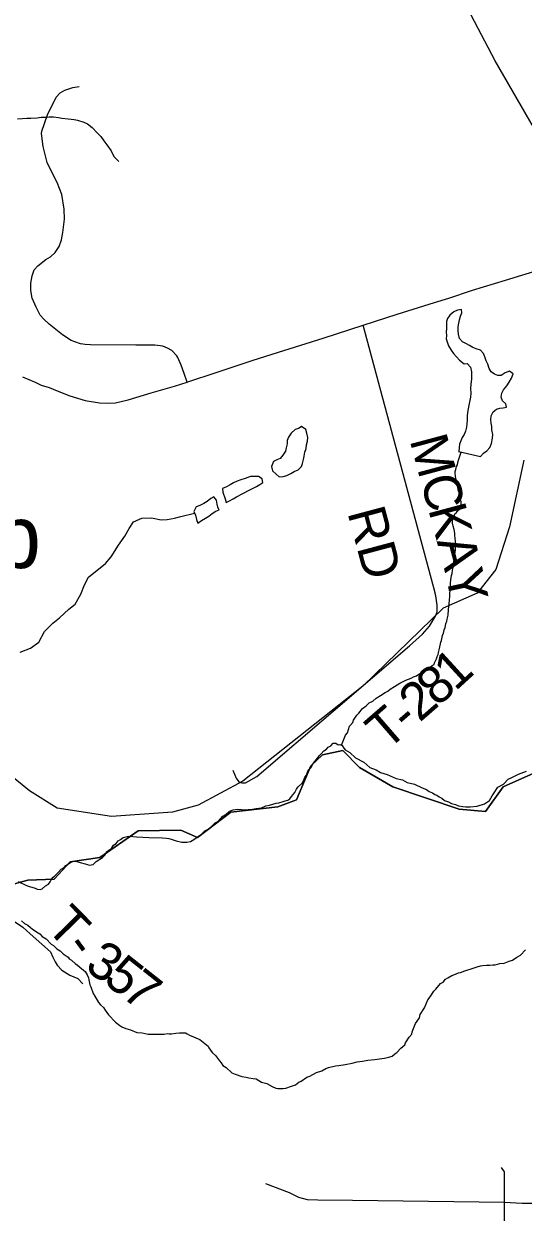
# Model space of a CAD drawing. Extents: x 0 to 34, y 0 to 22.
# Drawn here: x 5.489 to 6.245, y 18.554 to 20.352 of the extents above; entities that cross this region are included whole.
import ezdxf

# ---------------------------------------------------------------- set-up
doc = ezdxf.new("R2010")
doc.units = 0
for name, color, linetype in [('GM_X_Corporation', 7, 'Continuous'), ('GM_X_Minor_Lake', 7, 'Continuous'), ('GM_X_Minor_Lake_Text', 7, 'Continuous'), ('GM_X_Minor_River', 7, 'Continuous'), ('GM_X_Rail_Line', 7, 'Continuous'), ('GM_X_Township_Road', 7, 'Continuous'), ('GM_X_Township_Road_Text', 7, 'Continuous'), ('GM_X_US_Route', 7, 'Continuous')]:
    doc.layers.add(name, color=color, linetype=linetype)

msp = doc.modelspace()

# ---------------------------------------------------------------- linework, layer by layer
at = {"layer": 'GM_X_Corporation'}
for points in [[(6.2834, 19.2286), (6.2142, 19.1977), (6.1875, 19.1605), (6.148, 19.1641), (6.0474, 19.1975), (5.9969, 19.2271), (5.9718, 19.2529), (5.9409, 19.2461), (5.9236, 19.2297), (5.9019, 19.178), (5.8737, 19.1674), (5.8025, 19.1593), (5.7522, 19.121), (5.7269, 19.1323), (5.6622, 19.1314), (5.6043, 19.0909), (5.5594, 19.0843), (5.535, 19.0581), (5.4955, 19.0564), (5.4436, 19.0427)], [(5.4436, 19.0427), (5.4955, 19.0564), (5.535, 19.0581), (5.5594, 19.0843), (5.6043, 19.0909), (5.6622, 19.1314), (5.7269, 19.1323), (5.7522, 19.121), (5.8025, 19.1593), (5.8737, 19.1674), (5.9019, 19.178), (5.9236, 19.2297), (5.9409, 19.2461), (5.9718, 19.2529), (5.9969, 19.2271), (6.0474, 19.1975), (6.148, 19.1641), (6.1875, 19.1605), (6.2142, 19.1977), (6.2834, 19.2286)]]:
    msp.add_lwpolyline(points, dxfattribs=at)
at = {"layer": 'GM_X_Minor_Lake'}
for p, q in [((5.9096, 19.7426), (5.9046, 19.7398)), ((5.8464, 19.6549), (5.8509, 19.6578))]:
    msp.add_line(p, q, dxfattribs=at)
for points in [[(6.18, 19.6976), (6.1849, 19.7023), (6.1899, 19.706), (6.1945, 19.7109), (6.1969, 19.7169), (6.1981, 19.7249), (6.1986, 19.7306), (6.1975, 19.7378), (6.1972, 19.7428), (6.1962, 19.7477), (6.1958, 19.7526), (6.1963, 19.7587), (6.1994, 19.7651), (6.2044, 19.7692), (6.2094, 19.7703), (6.2143, 19.771), (6.2197, 19.772), (6.2182, 19.777), (6.2134, 19.7816), (6.2112, 19.7873), (6.2124, 19.7934), (6.2147, 19.7983), (6.2198, 19.8043), (6.2236, 19.8099), (6.2268, 19.8156), (6.2295, 19.8224), (6.2239, 19.8266), (6.2174, 19.8237), (6.2112, 19.82), (6.2063, 19.8201), (6.2014, 19.822), (6.1965, 19.8255), (6.1931, 19.8305), (6.191, 19.837), (6.1887, 19.842), (6.1869, 19.8481), (6.1847, 19.853), (6.1799, 19.8584), (6.1738, 19.86), (6.1685, 19.8624), (6.1636, 19.8651), (6.1579, 19.8682), (6.1527, 19.871), (6.1482, 19.876), (6.1467, 19.8824), (6.1464, 19.8881), (6.1465, 19.8935), (6.1474, 19.8991), (6.1482, 19.9041), (6.1498, 19.9094), (6.1518, 19.9146), (6.1514, 19.9196), (6.1454, 19.9189), (6.14, 19.916), (6.1338, 19.9111), (6.13, 19.9062), (6.1288, 19.9013), (6.1286, 19.8911), (6.1282, 19.8854), (6.1285, 19.8804), (6.1284, 19.8755), (6.1295, 19.8706), (6.1317, 19.8648), (6.1358, 19.8583), (6.1391, 19.8529), (6.144, 19.8483), (6.1485, 19.8429), (6.1552, 19.8375), (6.1602, 19.8378), (6.165, 19.8324), (6.1665, 19.8256), (6.1663, 19.8142), (6.1654, 19.8066), (6.165, 19.8002), (6.1653, 19.7933), (6.1648, 19.7873), (6.164, 19.782), (6.1627, 19.7752), (6.1615, 19.7695), (6.1607, 19.7638), (6.1602, 19.7585), (6.1601, 19.7528), (6.1597, 19.7467), (6.1588, 19.7418), (6.1572, 19.7357), (6.1553, 19.7308), (6.1525, 19.7259), (6.1502, 19.721), (6.1486, 19.7161), (6.1481, 19.7112), (6.1473, 19.7047)], [(6.1799, 19.6975), (6.1849, 19.7023), (6.1899, 19.706), (6.1945, 19.7109), (6.1969, 19.7169), (6.1981, 19.7249), (6.1986, 19.7306), (6.1975, 19.7378), (6.1972, 19.7428), (6.1962, 19.7477), (6.1958, 19.7526), (6.1963, 19.7587), (6.1994, 19.7651), (6.2044, 19.7692), (6.2094, 19.7703), (6.2143, 19.771), (6.2197, 19.772), (6.2182, 19.777), (6.2134, 19.7816), (6.2112, 19.7873), (6.2124, 19.7934), (6.2147, 19.7983), (6.2198, 19.8043), (6.2236, 19.8099), (6.2268, 19.8156), (6.2295, 19.8224), (6.2239, 19.8266), (6.2174, 19.8237), (6.2112, 19.82), (6.2063, 19.8201), (6.2014, 19.822), (6.1965, 19.8255), (6.1931, 19.8305), (6.191, 19.837), (6.1887, 19.842), (6.1869, 19.8481), (6.1847, 19.853), (6.1799, 19.8584), (6.1738, 19.86), (6.1685, 19.8624), (6.1636, 19.8651), (6.1579, 19.8682), (6.1527, 19.871), (6.1482, 19.876), (6.1467, 19.8824), (6.1464, 19.8881), (6.1465, 19.8935), (6.1474, 19.8991), (6.1482, 19.9041), (6.1498, 19.9094), (6.1518, 19.9146), (6.1514, 19.9196), (6.1454, 19.9189), (6.14, 19.916), (6.1338, 19.9111), (6.13, 19.9062), (6.1288, 19.9013), (6.1286, 19.8911), (6.1282, 19.8854), (6.1285, 19.8804), (6.1284, 19.8755), (6.1295, 19.8706), (6.1317, 19.8648), (6.1358, 19.8583), (6.1391, 19.8529), (6.144, 19.8483), (6.1485, 19.8429), (6.1552, 19.8375), (6.1602, 19.8378), (6.165, 19.8324), (6.1665, 19.8256), (6.1663, 19.8142), (6.1654, 19.8066), (6.165, 19.8002), (6.1653, 19.7933), (6.1648, 19.7873), (6.164, 19.782), (6.1627, 19.7752), (6.1615, 19.7695), (6.1607, 19.7638), (6.1602, 19.7585), (6.1601, 19.7528), (6.1597, 19.7467), (6.1588, 19.7418), (6.1572, 19.7357), (6.1553, 19.7308), (6.1525, 19.7259), (6.1502, 19.721), (6.1486, 19.7161), (6.1481, 19.7112), (6.1473, 19.7044), (6.1477, 19.7044)], [(5.9099, 19.7428), (5.9046, 19.7398), (5.8996, 19.738), (5.8938, 19.7328), (5.8899, 19.7268), (5.8876, 19.7215), (5.8875, 19.7166), (5.8863, 19.7105), (5.8851, 19.7056), (5.8812, 19.6996), (5.8769, 19.6943), (5.872, 19.6925), (5.867, 19.6899), (5.8639, 19.6823), (5.8657, 19.6759), (5.8709, 19.6705), (5.8758, 19.6666), (5.8815, 19.6673), (5.8872, 19.6687), (5.893, 19.6717), (5.8983, 19.6746), (5.9041, 19.6772), (5.9094, 19.6821), (5.9107, 19.687), (5.9126, 19.693), (5.9135, 19.6979), (5.9143, 19.704), (5.9163, 19.7097), (5.9171, 19.715), (5.9184, 19.7207), (5.9188, 19.726), (5.9174, 19.7328), (5.9159, 19.7382), (5.9096, 19.7426)], [(5.9046, 19.7398), (5.8996, 19.738), (5.8938, 19.7328), (5.8899, 19.7268), (5.8876, 19.7215), (5.8875, 19.7166), (5.8863, 19.7105), (5.8851, 19.7056), (5.8812, 19.6996), (5.8769, 19.6943), (5.872, 19.6925), (5.867, 19.6899), (5.8639, 19.6823), (5.8657, 19.6759), (5.8709, 19.6705), (5.8758, 19.6666), (5.8815, 19.6673), (5.8872, 19.6687), (5.893, 19.6717), (5.8983, 19.6746), (5.9041, 19.6772), (5.9094, 19.6821), (5.9107, 19.687), (5.9126, 19.693), (5.9135, 19.6979), (5.9143, 19.704), (5.9163, 19.7097), (5.9171, 19.715), (5.9184, 19.7207), (5.9188, 19.726), (5.9174, 19.7328), (5.9159, 19.7382), (5.9096, 19.7426)], [(6.1473, 19.7047), (6.18, 19.6976)], [(5.8509, 19.6578), (5.8499, 19.6636), (5.8443, 19.6671), (5.8386, 19.6672), (5.8321, 19.6669), (5.8241, 19.6643), (5.8176, 19.6622), (5.8119, 19.66), (5.8065, 19.6574), (5.8015, 19.6544), (5.7958, 19.6515), (5.79, 19.6489), (5.7903, 19.6432), (5.794, 19.6333), (5.7954, 19.6279), (5.8004, 19.6301), (5.8058, 19.6331), (5.8108, 19.6364), (5.8207, 19.6416), (5.8314, 19.6468), (5.8414, 19.6519), (5.8464, 19.6549)], [(5.8509, 19.6578), (5.8499, 19.6636), (5.8443, 19.6671), (5.8386, 19.6672), (5.8321, 19.6669), (5.8241, 19.6643), (5.8176, 19.6622), (5.8119, 19.66), (5.8065, 19.6574), (5.8015, 19.6544), (5.7958, 19.6515), (5.79, 19.6489), (5.7903, 19.6432), (5.794, 19.6333), (5.7954, 19.6279), (5.8004, 19.6301), (5.8058, 19.6331), (5.8108, 19.6364), (5.8207, 19.6416), (5.8314, 19.6468), (5.8414, 19.6519), (5.8464, 19.6549), (5.851, 19.6579)], [(5.7845, 19.6173), (5.7828, 19.6205), (5.7817, 19.6255), (5.7807, 19.6312), (5.7769, 19.6362), (5.772, 19.6336), (5.7666, 19.6295), (5.7616, 19.6261), (5.7555, 19.6232), (5.7501, 19.621), (5.7466, 19.6142), (5.7488, 19.6085), (5.7506, 19.602), (5.7524, 19.5967), (5.7582, 19.6008), (5.7639, 19.6041), (5.7693, 19.6071), (5.7743, 19.6112), (5.7797, 19.6145), (5.7846, 19.6167)], [(5.7845, 19.6173), (5.7828, 19.6205), (5.7817, 19.6255), (5.7807, 19.6312), (5.7769, 19.6362), (5.772, 19.6336), (5.7666, 19.6295), (5.7616, 19.6261), (5.7555, 19.6232), (5.7501, 19.621), (5.7466, 19.6142), (5.7488, 19.6085), (5.7506, 19.602), (5.7524, 19.5967), (5.7582, 19.6008), (5.7639, 19.6041), (5.7693, 19.6071), (5.7743, 19.6112), (5.7797, 19.6145), (5.7846, 19.6167)], [(5.7846, 19.6167), (5.7845, 19.6173)], [(5.7845, 19.6173), (5.7847, 19.6167)]]:
    msp.add_lwpolyline(points, dxfattribs=at)
at = {"layer": 'GM_X_Minor_River'}
for points in [[(5.48, 20.208), (5.4937, 20.2089), (5.5001, 20.2092), (5.5093, 20.2098), (5.5154, 20.2104), (5.523, 20.2107), (5.5279, 20.211), (5.5344, 20.2109), (5.542, 20.21), (5.5469, 20.2091), (5.5564, 20.2082), (5.5655, 20.2073), (5.5704, 20.2061), (5.5799, 20.2032), (5.5855, 20.2005), (5.5926, 20.195), (5.6001, 20.1869), (5.6057, 20.1815), (5.6106, 20.1749), (5.615, 20.1688), (5.6217, 20.1599), (5.6254, 20.1511), (5.6332, 20.1437)], [(6.1452, 19.6847), (6.1456, 19.6882), (6.1468, 19.6919), (6.1484, 19.6965), (6.1509, 19.7039)], [(5.9699, 19.2607), (5.9759, 19.2758), (5.9787, 19.2792), (5.9822, 19.2894), (5.9869, 19.295), (5.9881, 19.2984), (5.9932, 19.3063), (5.9959, 19.3093), (6.0017, 19.316), (6.0071, 19.3201), (6.0117, 19.3246), (6.0171, 19.3275), (6.0221, 19.3316), (6.0287, 19.3361), (6.036, 19.3405), (6.0398, 19.3424), (6.0436, 19.3453), (6.0498, 19.3494), (6.0579, 19.3546), (6.0674, 19.359), (6.0755, 19.3619), (6.0789, 19.3641), (6.0835, 19.3656), (6.0897, 19.37), (6.0943, 19.3715), (6.0977, 19.3737), (6.1004, 19.3748), (6.1039, 19.3785), (6.107, 19.3811), (6.11, 19.3826), (6.1108, 19.3852), (6.1136, 19.3913), (6.1148, 19.3947), (6.116, 19.3977), (6.1168, 19.4011), (6.1181, 19.4072), (6.1201, 19.4163), (6.1209, 19.4189), (6.1226, 19.4265), (6.1242, 19.4303), (6.125, 19.4352), (6.1266, 19.4386), (6.1278, 19.4443), (6.1294, 19.4484), (6.1295, 19.4515), (6.1311, 19.4575), (6.1316, 19.4659), (6.1329, 19.475), (6.133, 19.4803), (6.1335, 19.486), (6.1335, 19.4898), (6.134, 19.4951), (6.1344, 19.4982), (6.1345, 19.5024), (6.1349, 19.5058), (6.1354, 19.5107), (6.1363, 19.5175), (6.1371, 19.5202), (6.1379, 19.5255), (6.1388, 19.5297), (6.1388, 19.5323), (6.1401, 19.5407), (6.1409, 19.5448), (6.1414, 19.5494), (6.1418, 19.5521), (6.1423, 19.5566), (6.1424, 19.5642), (6.1421, 19.5684), (6.1418, 19.5741), (6.1415, 19.5775), (6.1411, 19.5814), (6.1405, 19.5871), (6.139, 19.592), (6.138, 19.5966), (6.1377, 19.6012), (6.1385, 19.6042), (6.1401, 19.6069), (6.1413, 19.6106), (6.144, 19.6125), (6.1459, 19.6159), (6.1486, 19.6177), (6.1502, 19.6204), (6.151, 19.6261), (6.1507, 19.6287), (6.1496, 19.6329), (6.1483, 19.6417), (6.1468, 19.6448), (6.1457, 19.6505), (6.1447, 19.6543), (6.1436, 19.66), (6.1429, 19.6635), (6.1422, 19.6688), (6.1419, 19.6719), (6.142, 19.6749), (6.1428, 19.6776), (6.1436, 19.6821), (6.1452, 19.6847)], [(5.4838, 19.4015), (5.4995, 19.4073), (5.5118, 19.4166), (5.5208, 19.4328), (5.5332, 19.4451), (5.5432, 19.4533), (5.5572, 19.4664), (5.5672, 19.4742), (5.5758, 19.4889), (5.581, 19.5032), (5.5873, 19.5149), (5.6128, 19.5354), (5.6213, 19.5455), (5.6327, 19.5631), (5.642, 19.577), (5.6487, 19.5887), (5.655, 19.5985), (5.668, 19.604), (5.6825, 19.6045), (5.6969, 19.6015), (5.7064, 19.6021), (5.7171, 19.6042), (5.7266, 19.6067), (5.7476, 19.6117)], [(5.9261, 19.2314), (5.9296, 19.2359), (5.9335, 19.2412), (5.9366, 19.2449), (5.9393, 19.2475), (5.9432, 19.2524), (5.9474, 19.2546), (5.9498, 19.2576), (5.9536, 19.2598), (5.9575, 19.2636), (5.9613, 19.2639), (5.9647, 19.2611), (5.9673, 19.2619), (5.9707, 19.2603), (5.9733, 19.2564), (5.9756, 19.2537), (5.9827, 19.2498), (5.9913, 19.2417), (6.0038, 19.235), (6.0128, 19.2272), (6.0222, 19.2232), (6.029, 19.2193), (6.0392, 19.2165), (6.0528, 19.2105), (6.0622, 19.2081), (6.0694, 19.2045), (6.0804, 19.2017), (6.0917, 19.1962), (6.0985, 19.1937), (6.1026, 19.1906), (6.1075, 19.1886), (6.1109, 19.1863), (6.1143, 19.1851), (6.1177, 19.1824), (6.1218, 19.1804), (6.1256, 19.1773), (6.1316, 19.1753), (6.1365, 19.1725), (6.1422, 19.1709), (6.1467, 19.1689), (6.1536, 19.1681), (6.1581, 19.1676), (6.1646, 19.1675), (6.1749, 19.1684), (6.1863, 19.172), (6.1936, 19.1769), (6.1979, 19.184), (6.1999, 19.187), (6.2065, 19.1972), (6.215, 19.202), (6.2219, 19.2095), (6.2277, 19.212), (6.2376, 19.2168), (6.2415, 19.2182), (6.2495, 19.2215)], [(5.481, 19.0544), (5.4935, 19.0484), (5.498, 19.0468), (5.5063, 19.0444), (5.5097, 19.0432), (5.5143, 19.0427), (5.5173, 19.0435), (5.5223, 19.0479), (5.5266, 19.0505), (5.5293, 19.0543), (5.5324, 19.0599), (5.5355, 19.0625), (5.5409, 19.0678), (5.5456, 19.0734), (5.5502, 19.0756), (5.5529, 19.079), (5.5571, 19.0812), (5.5606, 19.0838), (5.5648, 19.0852), (5.5697, 19.0848), (5.5746, 19.0831), (5.5822, 19.0815), (5.5856, 19.0803), (5.5883, 19.0795), (5.594, 19.0801), (5.5986, 19.0846), (5.6082, 19.0909), (5.6125, 19.095), (5.6137, 19.0988), (5.6179, 19.1018), (5.6218, 19.1044), (5.6249, 19.1096), (5.6291, 19.1122), (5.6318, 19.116), (5.6357, 19.1182), (5.6395, 19.1212), (5.6476, 19.1233), (5.654, 19.1228), (5.6597, 19.122), (5.6696, 19.1214), (5.6783, 19.1209), (5.6988, 19.1205), (5.7053, 19.12), (5.7087, 19.1196), (5.7121, 19.1188), (5.72, 19.116), (5.7284, 19.1139), (5.7329, 19.1138), (5.736, 19.1142), (5.7413, 19.1152), (5.7463, 19.1182), (5.7501, 19.1204), (5.7582, 19.1263), (5.7629, 19.1312), (5.7702, 19.1349), (5.7787, 19.1431), (5.784, 19.146), (5.7902, 19.1535), (5.7948, 19.1557), (5.8003, 19.161), (5.806, 19.1628), (5.8132, 19.1638), (5.8185, 19.1633), (5.822, 19.1632), (5.8288, 19.1635), (5.8322, 19.1634), (5.8406, 19.1652), (5.849, 19.1662), (5.8555, 19.1691), (5.8609, 19.1702), (5.8708, 19.173), (5.875, 19.1737), (5.8815, 19.1755), (5.8845, 19.1766), (5.8887, 19.1777), (5.8918, 19.1795), (5.8942, 19.1833), (5.8992, 19.1893), (5.9019, 19.1942), (5.9039, 19.1972), (5.9109, 19.2039), (5.9136, 19.2092), (5.9144, 19.2122), (5.9171, 19.2156), (5.9195, 19.2228), (5.9238, 19.2269), (5.9261, 19.2314)], [(5.4857, 18.9953), (5.4902, 18.9911), (5.4955, 18.9887), (5.4996, 18.9848), (5.5022, 18.9829), (5.5086, 18.9782), (5.5135, 18.9754), (5.5172, 18.9716), (5.5233, 18.968), (5.5307, 18.9599), (5.5341, 18.958), (5.5394, 18.9529), (5.5443, 18.9498), (5.5487, 18.9451), (5.5566, 18.9401), (5.5581, 18.9374), (5.5615, 18.9354), (5.5675, 18.93), (5.5701, 18.9284), (5.5742, 18.9249), (5.5795, 18.9206), (5.5821, 18.9183), (5.5851, 18.9133), (5.5873, 18.9087), (5.5876, 18.906), (5.5894, 18.8984), (5.5905, 18.8953), (5.5941, 18.885), (5.5967, 18.8812), (5.6022, 18.8716), (5.6052, 18.8681), (5.6097, 18.8638), (5.6123, 18.86), (5.6175, 18.8527), (5.628, 18.8418), (5.6347, 18.8368), (5.6377, 18.8348), (5.6434, 18.832), (5.6506, 18.8304), (5.6604, 18.8264), (5.6684, 18.8255), (5.6775, 18.8238), (5.698, 18.8235), (5.7018, 18.8238), (5.7064, 18.8245), (5.7094, 18.824), (5.7125, 18.8244), (5.7193, 18.8254), (5.725, 18.8257), (5.7307, 18.8259), (5.7338, 18.8255), (5.7364, 18.8239), (5.7398, 18.822), (5.7557, 18.8156), (5.7631, 18.8094), (5.7684, 18.8055), (5.7691, 18.8028), (5.7743, 18.7959), (5.7792, 18.7916), (5.7855, 18.7831), (5.7878, 18.7804), (5.7903, 18.7762), (5.7952, 18.7731), (5.8042, 18.7653), (5.8091, 18.7633), (5.819, 18.7597), (5.8258, 18.7585), (5.8296, 18.7576), (5.8364, 18.7568), (5.8409, 18.7559), (5.8488, 18.7512), (5.8568, 18.7488), (5.8651, 18.7445), (5.8704, 18.7421), (5.8738, 18.7413), (5.8814, 18.7415), (5.8856, 18.7422), (5.894, 18.7451), (5.9005, 18.7469), (5.9051, 18.751), (5.9089, 18.7528), (5.9174, 18.7584), (5.922, 18.7602), (5.932, 18.7657), (5.94, 18.7682), (5.9461, 18.7719), (5.9503, 18.773), (5.961, 18.7759), (5.966, 18.7765), (5.9755, 18.7779), (5.9858, 18.78), (5.9938, 18.7818)], [(5.9938, 18.7818), (6.0018, 18.7828), (6.0095, 18.7845), (6.0201, 18.7855), (6.0308, 18.7868), (6.035, 18.7871), (6.0415, 18.7889), (6.0464, 18.7903), (6.0507, 18.7937), (6.0538, 18.7959), (6.0596, 18.8023), (6.0657, 18.8075), (6.0669, 18.8105), (6.0724, 18.8192), (6.0763, 18.8237), (6.0767, 18.8271), (6.0819, 18.8399), (6.0877, 18.8482), (6.0889, 18.8535), (6.0956, 18.8636), (6.1007, 18.8757), (6.1038, 18.8799), (6.1097, 18.8885), (6.1128, 18.8919), (6.1194, 18.9001), (6.1236, 18.9023), (6.1271, 18.9068), (6.1306, 18.9087), (6.1367, 18.9124), (6.1398, 18.9135), (6.1467, 18.9164), (6.1497, 18.9171), (6.1566, 18.9192), (6.1688, 18.9236), (6.1749, 18.9254), (6.1803, 18.9272), (6.1837, 18.9275), (6.189, 18.9278), (6.194, 18.9281), (6.1986, 18.9284), (6.2024, 18.9287), (6.2096, 18.9305), (6.2161, 18.9311), (6.2234, 18.9341), (6.2283, 18.9355), (6.2349, 18.9403), (6.2406, 18.9433), (6.2484, 18.9511)]]:
    msp.add_lwpolyline(points, dxfattribs=at)
at = {"layer": 'GM_X_Rail_Line'}
msp.add_lwpolyline([(6.2458, 19.6916), (6.2238, 19.5908), (6.2031, 19.5265), (6.1749, 19.4905), (6.1239, 19.468), (6.0022, 19.3502), (5.8206, 19.2063), (5.7529, 19.1701), (5.7143, 19.1592), (5.6222, 19.1528), (5.5397, 19.1654), (5.498, 19.1918), (5.4679, 19.2162)], dxfattribs=at)
at = {"layer": 'GM_X_Township_Road'}
msp.add_line((6.1114, 19.4912), (6.0025, 19.8962), dxfattribs=at)
for points in [[(6.367, 20.0102), (6.2024, 20.2959), (6.1451, 20.4046)], [(5.7363, 19.81), (5.7319, 19.8228), (5.7273, 19.8356), (5.7225, 19.8472), (5.7208, 19.8498), (5.7131, 19.8575), (5.7069, 19.8614), (5.6995, 19.8643), (5.6876, 19.866), (5.6589, 19.8657), (5.5901, 19.8663), (5.5819, 19.8668), (5.5751, 19.8677), (5.5666, 19.8708), (5.5612, 19.8728), (5.5478, 19.8816), (5.5279, 19.8975), (5.5194, 19.9052), (5.5143, 19.9111), (5.508, 19.9234), (5.5021, 19.937), (5.4998, 19.9486), (5.4998, 19.9594), (5.5018, 19.9708), (5.5049, 19.9799), (5.5106, 19.9858), (5.5225, 19.9955), (5.5296, 19.9995), (5.5367, 20.0057), (5.5427, 20.0148), (5.5461, 20.025), (5.5484, 20.0361), (5.5509, 20.0563), (5.5504, 20.0714), (5.5467, 20.0935), (5.5399, 20.1117), (5.5285, 20.1333), (5.5245, 20.1421), (5.5188, 20.1662), (5.516, 20.1858), (5.5166, 20.1895), (5.5254, 20.2139), (5.5381, 20.2409), (5.5441, 20.2472), (5.5512, 20.2514), (5.5637, 20.2557), (5.5731, 20.257)], [(5.8148, 19.2052), (5.8193, 19.204), (5.8246, 19.2038), (5.8416, 19.2133), (6.0729, 19.4111), (6.0923, 19.4285), (6.1029, 19.4407), (6.112, 19.4561), (6.1144, 19.4625), (6.1147, 19.4723), (6.1128, 19.4864), (6.1117, 19.4902), (6.1114, 19.4912)], [(5.8054, 19.2229), (5.8104, 19.2107), (5.8148, 19.2052)], [(5.4473, 19.0042), (5.4483, 19.0038), (5.4633, 18.9999), (5.4766, 18.9931), (5.4878, 18.9854), (5.499, 18.9752), (5.5165, 18.9597), (5.5296, 18.9482), (5.5332, 18.94), (5.5367, 18.933), (5.5396, 18.9278), (5.5466, 18.9205), (5.5589, 18.913), (5.5708, 18.9076), (5.5788, 18.8996)], [(5.8547, 18.5979), (5.8909, 18.5841), (5.905, 18.5769), (5.9177, 18.5736), (5.9343, 18.5729), (5.9865, 18.5725), (6.2165, 18.5693), (6.2433, 18.5678), (6.2723, 18.5678), (6.2915, 18.5664), (6.3071, 18.5678), (6.319, 18.5711), (6.3321, 18.5816), (6.3425, 18.5956), (6.3481, 18.6528), (6.3457, 18.6879)], [(6.2584, 18.389), (6.2181, 18.4696), (6.2158, 18.4819), (6.2165, 18.5693), (6.2163, 18.6154), (6.2119, 18.6221)]]:
    msp.add_lwpolyline(points, dxfattribs=at)
at = {"layer": 'GM_X_US_Route'}
msp.add_lwpolyline([(5.4873, 19.8179), (5.5063, 19.8097), (5.5156, 19.8053), (5.5276, 19.8016), (5.5398, 19.7965), (5.559, 19.7892), (5.5821, 19.7822), (5.604, 19.7784), (5.6153, 19.7778), (5.628, 19.7787), (5.6471, 19.783), (5.6822, 19.7938), (5.7174, 19.8037), (5.7363, 19.81), (5.7391, 19.811), (5.7789, 19.824), (5.8363, 19.8429), (5.8824, 19.8577), (5.9423, 19.8765), (6.0025, 19.8962), (6.054, 19.9126), (6.1105, 19.9302), (6.1321, 19.9366), (6.1682, 19.949), (6.2178, 19.9642), (6.2737, 19.9811)], dxfattribs=at)

# ---------------------------------------------------------------- texts
at = {"layer": 'GM_X_Minor_Lake_Text'}
msp.add_text('Hilltop', height=0.09469, rotation=359.9965, dxfattribs=at).set_placement((5.1633, 19.5287))
at = {"layer": 'GM_X_Township_Road_Text'}
for s, height, rotation, p in [('M', 0.0568, 284.9976, (6.0727, 19.7224)), ('C', 0.0568, 284.9943, (6.0887, 19.6628)), ('RD', 0.05682, 284.9946, (5.9785, 19.613)), ('K', 0.0568, 284.9958, (6.1008, 19.6178)), ('A', 0.0568, 284.9701, (6.1137, 19.5695)), ('Y', 0.0568, 282.0436, (6.1264, 19.5219)), ('1', 0.0568, 42.4581, (6.1419, 19.3415)), ('8', 0.0568, 41.3317, (6.1147, 19.3176)), ('2', 0.0568, 41.0071, (6.088, 19.2944)), ('T', 0.0568, 40.9025, (6.0382, 19.2512)), ('-', 0.0568, 40.9241, (6.0703, 19.2791)), ('T', 0.0568, 314.4452, (5.5209, 18.984)), ('-', 0.0568, 306.174, (5.5492, 18.9554)), ('3', 0.0568, 327.4864, (5.5796, 18.921)), ('5', 0.0568, 321.7477, (5.6076, 18.9032)), ('7', 0.0568, 321.7477, (5.6349, 18.8817))]:
    msp.add_text(s, height=height, rotation=rotation, dxfattribs=at).set_placement(p)

doc.saveas('drawing.dxf')
